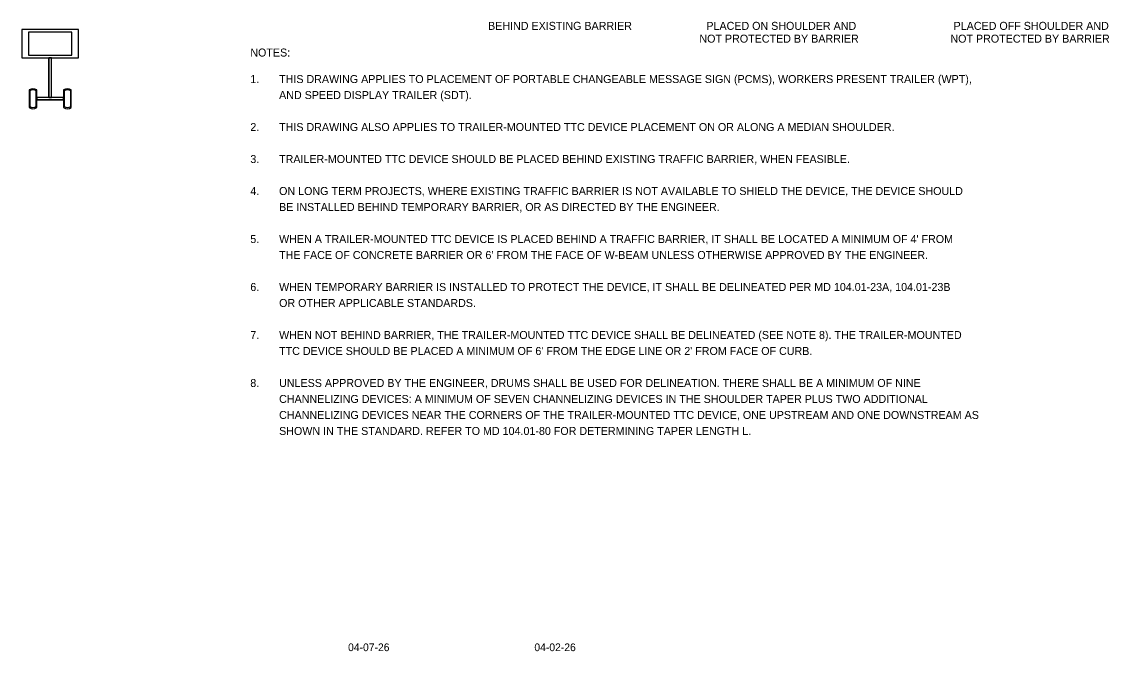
# Model space of a CAD drawing. Extents: x 9 to 25.8, y 6 to 22.7.
# Drawn here: x 10.69 to 19.12, y 6.13 to 11.02 of the extents above; entities that cross this region are included whole.
import ezdxf

# ---------------------------------------------------------------- set-up
doc = ezdxf.new("R2010")
doc.units = 0
for name, color, linetype in [('Default', 7, 'Continuous'), ('DETL-NOTE', 7, 'Continuous'), ('TTLB-TEXT', 7, 'Continuous')]:
    doc.layers.add(name, color=color, linetype=linetype)

msp = doc.modelspace()

# ---------------------------------------------------------------- linework, layer by layer
at = {"layer": 'Default'}
for p, q in [((10.8964, 10.4313), (10.8964, 10.7387)), ((10.8964, 10.7387), (10.8964, 10.4313)), ((10.8964, 10.7387), (10.9152, 10.7387)), ((10.8964, 10.7387), (10.8964, 10.4313)), ((10.9152, 10.7387), (10.8964, 10.7387)), ((10.9152, 10.4313), (10.9152, 10.7387)), ((10.9152, 10.4313), (10.9152, 10.7387)), ((10.9152, 10.4313), (10.9152, 10.7387)), ((10.743, 10.4901), (10.743, 10.3538)), ((10.7466, 10.4817), (10.7466, 10.3621)), ((10.7978, 10.3621), (10.7978, 10.4817)), ((10.8014, 10.3538), (10.8014, 10.4901)), ((11.0102, 10.4901), (11.0102, 10.3538)), ((11.0138, 10.4817), (11.0138, 10.3621)), ((11.0651, 10.3621), (11.0651, 10.4817)), ((11.0686, 10.3538), (11.0686, 10.4901)), ((11.0102, 10.4313), (10.8014, 10.4313)), ((11.0102, 10.4313), (10.8014, 10.4313)), ((10.8014, 10.4313), (10.8014, 10.4125)), ((10.8014, 10.4313), (10.8014, 10.4125)), ((10.8964, 10.4313), (10.8014, 10.4313)), ((11.0102, 10.4125), (10.8014, 10.4125)), ((10.8014, 10.4125), (11.0102, 10.4125)), ((10.8014, 10.4125), (11.0102, 10.4125)), ((10.8964, 10.4313), (10.9152, 10.4313)), ((10.9152, 10.4313), (10.8964, 10.4313)), ((10.8964, 10.4313), (10.9152, 10.4313)), ((11.0102, 10.4313), (10.9152, 10.4313)), ((11.0102, 10.4125), (11.0102, 10.4313)), ((11.0102, 10.4125), (11.0102, 10.4313))]:
    msp.add_line(p, q, dxfattribs=at)
for points in [[(11.1265, 10.9596), (10.6851, 10.9596), (10.6851, 10.7387), (11.1265, 10.7387)], [(11.0734, 10.9382), (10.7383, 10.9382), (10.7383, 10.7601), (11.0734, 10.7601)]]:
    msp.add_lwpolyline(points, close=True, dxfattribs=at)
for centre, radius, start, end in [((10.7722, 10.4491), 0.0503, 54.52623, 125.47377), ((10.7722, 10.4458), 0.0441, 54.52623, 125.47377), ((11.0394, 10.4491), 0.0503, 54.52623, 125.47377), ((11.0394, 10.4458), 0.0441, 54.52623, 125.47377), ((10.7722, 10.3947), 0.0503, 234.52623, 305.47377), ((10.7722, 10.3981), 0.0441, 234.52623, 305.47377), ((11.0394, 10.3947), 0.0503, 234.52623, 305.47377), ((11.0394, 10.3981), 0.0441, 234.52623, 305.47377)]:
    msp.add_arc(centre, radius, start, end, dxfattribs=at)

# ---------------------------------------------------------------- texts
at = {"layer": 'DETL-NOTE'}
for s, height, p in [('BEHIND EXISTING BARRIER', 0.062069, (14.302, 10.9561)), ('PLACED ON SHOULDER AND', 0.062069, (15.9951, 10.9561)), ('PLACED OFF SHOULDER AND', 0.062069, (17.9128, 10.9561)), ('NOT PROTECTED BY BARRIER', 0.062069, (15.941, 10.8568)), ('NOT PROTECTED BY BARRIER', 0.062069, (17.8879, 10.8568)), ('NOTES:', 0.06207, (12.4579, 10.7489)), ('1.', 0.06207, (12.4579, 10.5433)), ('THIS DRAWING APPLIES TO PLACEMENT OF PORTABLE CHANGEABLE MESSAGE SIGN (PCMS), WORKERS PRESENT TRAILER (WPT), ', 0.062069, (12.6812, 10.5433)), ('AND SPEED DISPLAY TRAILER (SDT).', 0.062069, (12.6812, 10.4192)), ('2.', 0.06207, (12.4579, 10.1709)), ('THIS DRAWING ALSO APPLIES TO TRAILER-MOUNTED TTC DEVICE PLACEMENT ON OR ALONG A MEDIAN SHOULDER.', 0.062069, (12.6812, 10.1709)), ('3.', 0.06207, (12.4579, 9.9226)), ('TRAILER-MOUNTED TTC DEVICE SHOULD BE PLACED BEHIND EXISTING TRAFFIC BARRIER, WHEN FEASIBLE. ', 0.062069, (12.6812, 9.9226)), ('4.', 0.06207, (12.4579, 9.6744)), ('ON LONG TERM PROJECTS, WHERE EXISTING TRAFFIC BARRIER IS NOT AVAILABLE TO SHIELD THE DEVICE, THE DEVICE SHOULD ', 0.062069, (12.6812, 9.6744)), ('BE INSTALLED BEHIND TEMPORARY BARRIER, OR AS DIRECTED BY THE ENGINEER. ', 0.062069, (12.6812, 9.5502)), ('5.', 0.06207, (12.4579, 9.3019)), ("WHEN A TRAILER-MOUNTED TTC DEVICE IS PLACED BEHIND A TRAFFIC BARRIER, IT SHALL BE LOCATED A MINIMUM OF 4' FROM ", 0.062069, (12.6812, 9.3019)), ("THE FACE OF CONCRETE BARRIER OR 6' FROM THE FACE OF W-BEAM UNLESS OTHERWISE APPROVED BY THE ENGINEER.", 0.062069, (12.6812, 9.1778)), ('6.', 0.06207, (12.4579, 8.9295)), ('WHEN TEMPORARY BARRIER IS INSTALLED TO PROTECT THE DEVICE, IT SHALL BE DELINEATED PER MD 104.01-23A, 104.01-23B ', 0.062069, (12.6812, 8.9295)), ('OR OTHER APPLICABLE STANDARDS.', 0.062069, (12.6812, 8.8054)), ('7.', 0.06207, (12.4579, 8.5571)), ('WHEN NOT BEHIND BARRIER, THE TRAILER-MOUNTED TTC DEVICE SHALL BE DELINEATED (SEE NOTE 8). THE TRAILER-MOUNTED ', 0.062069, (12.6812, 8.5571)), ("TTC DEVICE SHOULD BE PLACED A MINIMUM OF 6' FROM THE EDGE LINE OR 2' FROM FACE OF CURB.", 0.062069, (12.6812, 8.433)), ('8.', 0.06207, (12.4579, 8.1847)), ('UNLESS APPROVED BY THE ENGINEER, DRUMS SHALL BE USED FOR DELINEATION. THERE SHALL BE A MINIMUM OF NINE ', 0.062069, (12.6812, 8.1847)), ('CHANNELIZING DEVICES: A MINIMUM OF SEVEN CHANNELIZING DEVICES IN THE SHOULDER TAPER PLUS TWO ADDITIONAL ', 0.062069, (12.6812, 8.0606)), ('CHANNELIZING DEVICES NEAR THE CORNERS OF THE TRAILER-MOUNTED TTC DEVICE, ONE UPSTREAM AND ONE DOWNSTREAM AS ', 0.062069, (12.6812, 7.9364)), ('SHOWN IN THE STANDARD. REFER TO MD 104.01-80 FOR DETERMINING TAPER LENGTH L.', 0.062069, (12.6812, 7.8123))]:
    msp.add_text(s, height=height, dxfattribs=at).set_placement(p)
at = {"layer": 'TTLB-TEXT'}
for s, p in [('04-07-26', (13.2162, 6.1344)), ('04-02-26', (14.6611, 6.1344))]:
    msp.add_text(s, height=0.06, dxfattribs=at).set_placement(p)

doc.saveas('drawing.dxf')
